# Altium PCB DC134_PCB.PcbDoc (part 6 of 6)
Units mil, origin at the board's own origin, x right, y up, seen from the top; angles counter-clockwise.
Board outline 4000 x 2750 mil, 6 copper layers (L1_Top Layer, L2_GND1, L3_Signal, L4_Plane, L5_GND2, L6_Bottom Layer), stack 60.4 mil thick; 404 components, 244 nets, 1547 pads, 694 vias.
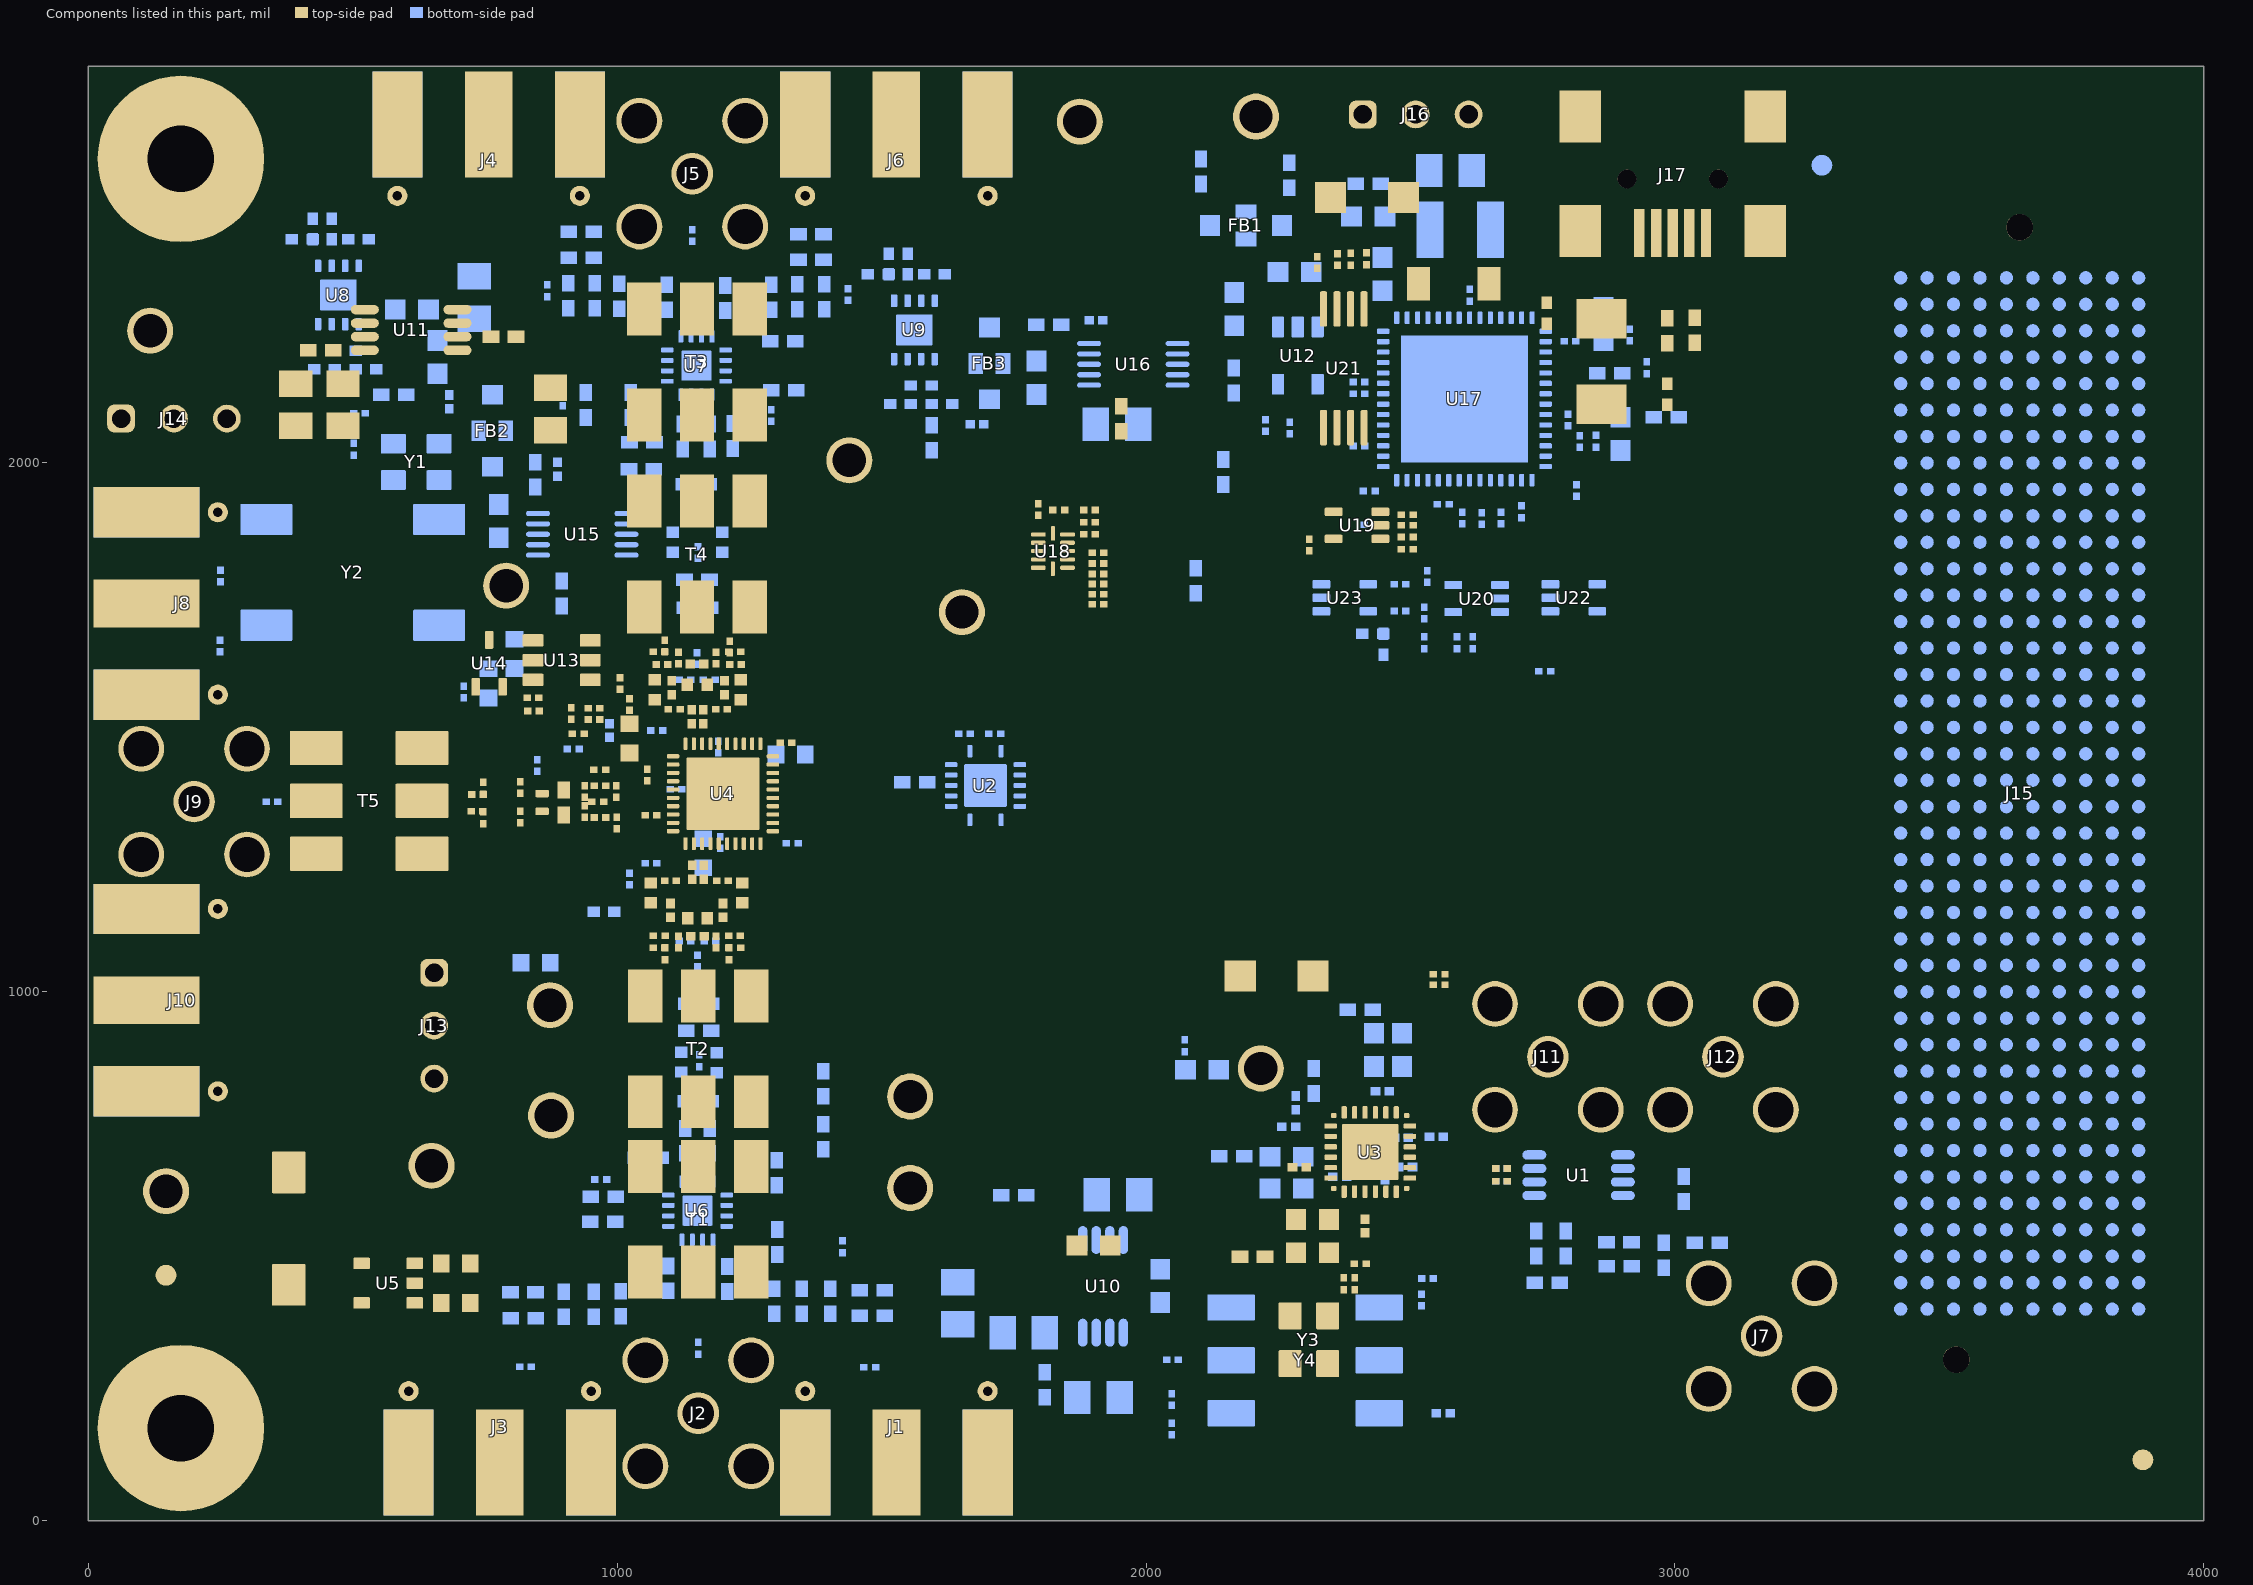
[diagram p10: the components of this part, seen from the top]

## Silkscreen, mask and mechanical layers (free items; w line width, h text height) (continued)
Drill Drawing:
  circle w10: c6400,-155.73 r16.58
  circle w10: c6400,-155.73 r27.63
  circle w10: c6400,-404.37 r27.63
  lines w10: 6372.37,-915.47 6386.18,-915.47 6386.18,-929.28 6413.81,-929.28 6413.81,-915.47 6427.62,-915.47 6427.62,-887.84 6413.81,-887.84 6413.81,-874.03 6386.18,-874.03 6386.18,-887.84 6372.37,-887.84 6372.37,-915.47 ; 6372.37,-804.96 6372.37,-791.15 6386.18,-777.33 6372.37,-763.52 6372.37,-749.71 6386.18,-749.71 6400,-763.52 6413.81,-749.71 6427.62,-749.71 6427.62,-763.52 6413.81,-777.33 6427.62,-791.15 6427.62,-804.96 6413.81,-804.96 6400,-791.15 6386.18,-804.96 6372.37,-804.96 ; 6372.37,-625.39 6427.62,-625.39 6400,-680.64 6372.37,-625.39 ; 6372.37,-542.51 6386.18,-542.51 6400,-556.32 6413.81,-542.51 6427.62,-542.51 6413.81,-528.69 6427.62,-514.88 6413.81,-514.88 6400,-501.07 6386.18,-514.88 6372.37,-514.88 6386.18,-528.69 6372.37,-542.51 ; 6372.37,-252.43 6427.62,-252.43 6400,-307.68 6372.37,-252.43 ; 6372.37,-59.04 6400,-45.23 6427.62,-59.04 6413.81,-31.41 6427.62,-3.79 6400,-17.6 6372.37,-3.79 6386.18,-31.41 6372.37,-59.04 ; 6372.37,65.28 6372.37,79.09 6386.18,92.91 6372.37,106.72 6372.37,120.53 6386.18,120.53 6400,106.72 6413.81,120.53 6427.62,120.53 6427.62,106.72 6413.81,92.91 6427.62,79.09 6427.62,65.28 6413.81,65.28 6400,79.09 6386.18,65.28 6372.37,65.28 ; 6372.37,189.6 6427.62,189.6 6427.62,244.85 6372.37,244.85 6372.37,189.6 ; 6372.37,313.92 6427.62,313.92 6427.62,369.17 6372.37,369.17 6372.37,313.92 ; 6383.42,-909.94 6391.71,-909.94 6391.71,-918.23 6408.28,-918.23 6408.28,-909.94 6416.57,-909.94 6416.57,-893.37 6408.28,-893.37 6408.28,-885.08 6391.71,-885.08 6391.71,-893.37 6383.42,-893.37 6383.42,-909.94 ; 6383.42,-793.91 6383.42,-785.62 6391.71,-777.33 6383.42,-769.05 6383.42,-760.76 6391.71,-760.76 6400,-769.05 6408.28,-760.76 6416.57,-760.76 6416.57,-769.05 6408.28,-777.33 6416.57,-785.62 6416.57,-793.91 6408.28,-793.91 6400,-785.62 6391.71,-793.91 6383.42,-793.91 ; 6383.42,-636.44 6416.57,-636.44 6400,-669.59 6383.42,-636.44 ; 6383.42,324.97 6416.57,324.97 6416.57,358.12 6383.42,358.12 6383.42,324.97
  lines w12: 6322.28,-966.58 10696.95,-966.58 ; 6322.28,400.94 10696.95,400.94 ; 6660.14,-1090.9 6660.14,525.26 ; 6992.14,-1090.9 6992.14,525.26 ; 7628.7,-1090.9 7628.7,525.26 ; 7887.84,-1090.9 7887.84,525.26 ; 8263,-1090.9 8263,525.26 ; 8940.52,-1090.9 8940.52,525.26 ; 9378.29,-1090.9 9378.29,525.26 ; 10284.77,-1090.9 10284.77,525.26 ; 6322.28,-1090.9 10696.95,-1090.9 10696.95,525.26 6322.28,525.26 6322.28,-1090.9
  text "Symbol" at 6396.87,438.24 h72
  text "Quantity" at 6697.44,438.24 h72
  text "Finished Hole Size" at 7029.44,438.24 h72
  text "Plated" at 7666,438.24 h72
  text "Hole Type" at 7925.14,438.24 h72
  text "Routed Path Length" at 8300.3,438.24 h72
  text "Hole Length" at 8977.82,438.24 h72
  text "Drill Layer Pair" at 9415.58,438.24 h72
  text "Tolerance" at 10322.06,438.24 h72
  text "2" at 6697.44,313.92 h60
  text "35.43mil (0.900mm)" at 7029.44,313.92 h60
  text "NPTH" at 7666,313.92 h60
  text "Round" at 7925.14,313.92 h60
  text "-" at 8300.3,313.92 h60
  text "-" at 8977.82,313.92 h60
  text "L1_Top Layer - L6_Bottom Layer" at 9415.58,313.92 h60
  text "2" at 6697.44,189.6 h60
  text "50.00mil (1.270mm)" at 7029.44,189.6 h60
  text "NPTH" at 7666,189.6 h60
  text "Round" at 7925.14,189.6 h60
  text "-" at 8300.3,189.6 h60
  text "-" at 8977.82,189.6 h60
  text "L1_Top Layer - L6_Bottom Layer" at 9415.58,189.6 h60
  text "62" at 6697.44,65.28 h60
  text "7.87mil (0.200mm)" at 7029.44,65.28 h60
  text "PTH" at 7666,65.28 h60
  text "Round" at 7925.14,65.28 h60
  text "-" at 8300.3,65.28 h60
  text "-" at 8977.82,65.28 h60
  text "L1_Top Layer - L6_Bottom Layer" at 9415.58,65.28 h60
  text "+/- 3 mil" at 10322.06,65.28 h60
  text "450" at 6697.44,-59.04 h60
  text "8.00mil (0.203mm)" at 7029.44,-59.04 h60
  text "PTH" at 7666,-59.04 h60
  text "Round" at 7925.14,-59.04 h60
  text "-" at 8300.3,-59.04 h60
  text "-" at 8977.82,-59.04 h60
  text "L1_Top Layer - L6_Bottom Layer" at 9415.58,-59.04 h60
  text "182" at 6697.44,-183.36 h60
  text "10.00mil (0.254mm)" at 7029.44,-183.36 h60
  text "PTH" at 7666,-183.36 h60
  text "Round" at 7925.14,-183.36 h60
  text "-" at 8300.3,-183.36 h60
  text "-" at 8977.82,-183.36 h60
  text "L1_Top Layer - L6_Bottom Layer" at 9415.58,-183.36 h60
  text "+/- 3 mil" at 10322.06,-183.36 h60
  text "12" at 6697.44,-307.68 h60
  text "18.00mil (0.457mm)" at 7029.44,-307.68 h60
  text "PTH" at 7666,-307.68 h60
  text "Round" at 7925.14,-307.68 h60
  text "-" at 8300.3,-307.68 h60
  text "-" at 8977.82,-307.68 h60
  text "L1_Top Layer - L6_Bottom Layer" at 9415.58,-307.68 h60
  text "9" at 6697.44,-432 h60
  text "35.00mil (0.889mm)" at 7029.44,-432 h60
  text "PTH" at 7666,-432 h60
  text "Round" at 7925.14,-432 h60
  text "-" at 8300.3,-432 h60
  text "-" at 8977.82,-432 h60
  text "L1_Top Layer - L6_Bottom Layer" at 9415.58,-432 h60
  text "6" at 6697.44,-556.32 h60
  text "59.06mil (1.500mm)" at 7029.44,-556.32 h60
  text "PTH" at 7666,-556.32 h60
  text "Round" at 7925.14,-556.32 h60
  text "-" at 8300.3,-556.32 h60
  text "-" at 8977.82,-556.32 h60
  text "L1_Top Layer - L6_Bottom Layer" at 9415.58,-556.32 h60
  text "13" at 6697.44,-680.64 h60
  text "63.00mil (1.600mm)" at 7029.44,-680.64 h60
  text "PTH" at 7666,-680.64 h60
  text "Round" at 7925.14,-680.64 h60
  text "-" at 8300.3,-680.64 h60
  text "-" at 8977.82,-680.64 h60
  text "L1_Top Layer - L6_Bottom Layer" at 9415.58,-680.64 h60
  text "+/- 3 mil" at 10322.06,-680.64 h60
  text "24" at 6697.44,-804.96 h60
  text "66.93mil (1.700mm)" at 7029.44,-804.96 h60
  text "PTH" at 7666,-804.96 h60
  text "Round" at 7925.14,-804.96 h60
  text "-" at 8300.3,-804.96 h60
  text "-" at 8977.82,-804.96 h60
  text "L1_Top Layer - L6_Bottom Layer" at 9415.58,-804.96 h60
  text "2" at 6697.44,-929.28 h60
  text "125.98mil (3.200mm)" at 7029.44,-929.28 h60
  text "PTH" at 7666,-929.28 h60
  text "Round" at 7925.14,-929.28 h60
  text "-" at 8300.3,-929.28 h60
  text "-" at 8977.82,-929.28 h60
  text "L1_Top Layer - L6_Bottom Layer" at 9415.58,-929.28 h60
  text "764 Total" at 6697.44,-1053.6 h60
  text ".Layer_Name" at 577,-1885.49 h60
M17 Embedded Cavity:
  text ".Layer_Name" at 577,-1885.49 h60
M18 Embedded Assembly:
  text ".Layer_Name" at 577,-1885.49 h60
M19 Embedded Keepout:
  text ".Layer_Name" at 577,-1885.49 h60

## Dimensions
-25,0 to -25,2750 on M2 Board Dimensions
0,-25 to 4000,-25 on M2 Board Dimensions
0,-1427 to 1000,-1427 on M2 Board Dimensions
